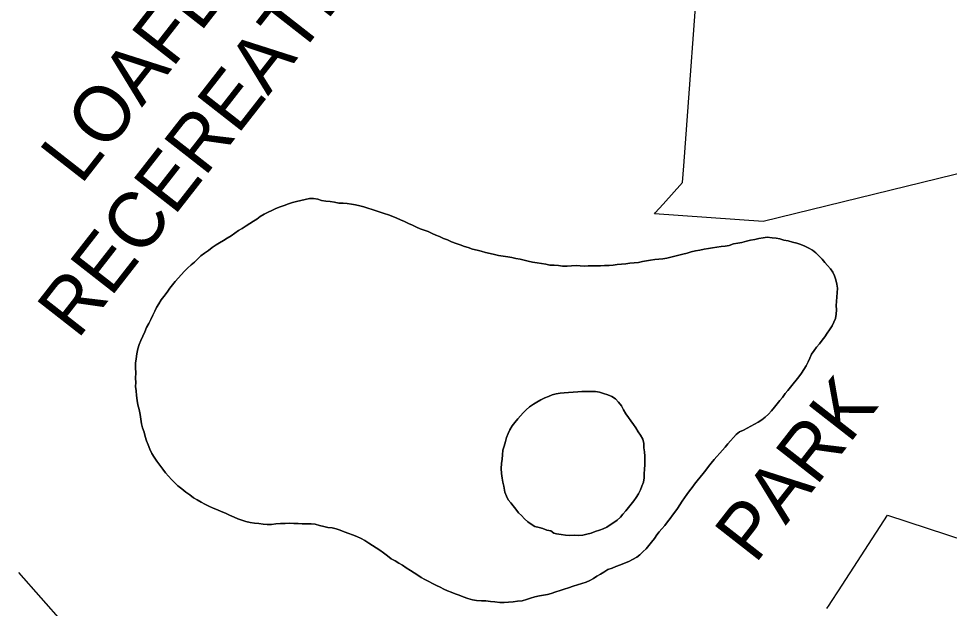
# Model space of a CAD drawing. Extents: x 586326 to 623965, y 4819854 to 4857850.
# Drawn here: x 596412.8 to 596748.3, y 4841778.5 to 4841991 of the extents above; entities that cross this region are included whole.
import ezdxf

# ---------------------------------------------------------------- set-up
doc = ezdxf.new("R2010")
doc.units = 0
for name, color, linetype in [('Park Lbls', 7, 'Continuous'), ('Park Outlines', 7, 'Continuous'), ('Rec Lbls', 7, 'Continuous')]:
    doc.layers.add(name, color=color, linetype=linetype)

msp = doc.modelspace()

# ---------------------------------------------------------------- linework, layer by layer
at = {"layer": 'Park Outlines'}
for points in [[(596784.29, 4841943.2), (596681.13, 4841917.86), (596641.99, 4841920.73), (596642.25, 4841921.02), (596645.09, 4841924.15), (596652.13, 4841931.92), (596652.57, 4841937.95), (596658.49, 4842018.07)], [(596704.13, 4841778.41), (596704.96, 4841779.69), (596705.79, 4841780.97), (596708.31, 4841784.85), (596725.99, 4841812.09), (596804.1, 4841786.56)], [(596412.71, 4841791.49), (596420.8, 4841782.34), (596428.89, 4841773.19)]]:
    msp.add_lwpolyline(points, dxfattribs=at)
for points in [[(596587.75, 4841780.62), (596586.22, 4841780.67), (596584.48, 4841780.85), (596582.85, 4841781.01), (596581.19, 4841781.17), (596579.62, 4841781.17), (596577.82, 4841781.29), (596576.41, 4841781.54), (596574.68, 4841782.11), (596573.01, 4841782.71), (596571.63, 4841783.23), (596570.12, 4841783.8), (596568.71, 4841784.38), (596567.37, 4841784.89), (596566.03, 4841785.45), (596564.69, 4841786.11), (596563.36, 4841786.77), (596562.02, 4841787.43), (596560.62, 4841788.19), (596559.23, 4841788.96), (596557.91, 4841789.68), (596556.66, 4841790.46), (596555.3, 4841791.32), (596554.03, 4841792.11), (596552.5, 4841793.11), (596551.15, 4841794.03), (596549.88, 4841794.82), (596548.53, 4841795.6), (596547.12, 4841796.4), (596545.73, 4841797.4), (596544.3, 4841798.53), (596542.97, 4841799.48), (596541.66, 4841800.3), (596540.34, 4841801.21), (596539.04, 4841802.06), (596537.53, 4841802.96), (596536.22, 4841803.65), (596534.71, 4841804.41), (596533.18, 4841804.97), (596531.8, 4841805.52), (596530.1, 4841806.14), (596528.63, 4841806.72), (596527.2, 4841807.21), (596525.76, 4841807.51), (596524.22, 4841807.64), (596522.77, 4841808.02), (596521.25, 4841808.4), (596519.72, 4841808.81), (596518.2, 4841808.96), (596516.61, 4841808.95), (596515.04, 4841809.03), (596513.51, 4841809.08), (596512, 4841809.11), (596510.47, 4841809.16), (596508.83, 4841809.15), (596507.13, 4841809.12), (596505.5, 4841808.92), (596503.89, 4841808.77), (596502.34, 4841808.7), (596500.88, 4841808.8), (596499.33, 4841809.09), (596497.76, 4841809.27), (596496.3, 4841809.45), (596494.63, 4841809.83), (596493.22, 4841810.26), (596491.82, 4841810.79), (596490.45, 4841811.36), (596488.82, 4841812.11), (596487.34, 4841812.78), (596485.83, 4841813.4), (596484.43, 4841813.97), (596482.88, 4841814.64), (596481.3, 4841815.4), (596479.92, 4841816.09), (596478.54, 4841816.79), (596477.08, 4841817.62), (596475.87, 4841818.4), (596474.44, 4841819.39), (596473.06, 4841820.41), (596471.59, 4841821.58), (596470.16, 4841822.72), (596468.95, 4841823.82), (596467.92, 4841824.9), (596466.8, 4841826.16), (596465.68, 4841827.37), (596464.73, 4841828.64), (596463.69, 4841830.09), (596462.55, 4841831.54), (596461.66, 4841832.95), (596460.84, 4841834.36), (596460.12, 4841835.92), (596459.49, 4841837.47), (596458.92, 4841838.91), (596458.44, 4841840.42), (596457.99, 4841842.06), (596457.47, 4841843.6), (596457.07, 4841845.02), (596456.82, 4841846.64), (596456.56, 4841848.38), (596456.24, 4841850.13), (596455.8, 4841851.82), (596455.48, 4841853.39), (596455.28, 4841855.16), (596455.1, 4841856.86), (596454.95, 4841858.41), (596454.98, 4841859.88), (596454.96, 4841861.5), (596455.01, 4841863.36), (596454.93, 4841865.18), (596454.94, 4841866.84), (596455.12, 4841868.45), (596455.44, 4841870.27), (596455.75, 4841872), (596456.24, 4841873.57), (596456.85, 4841875.03), (596457.6, 4841876.62), (596458.28, 4841878.2), (596458.92, 4841879.69), (596459.72, 4841881.21), (596460.42, 4841882.55), (596461.2, 4841884.12), (596461.9, 4841885.64), (596462.54, 4841886.91), (596463.27, 4841888.19), (596464.2, 4841889.64), (596465.13, 4841890.95), (596466.3, 4841892.46), (596467.34, 4841893.86), (596468.3, 4841895.07), (596469.24, 4841896.25), (596470.37, 4841897.58), (596471.39, 4841898.73), (596472.55, 4841900), (596473.7, 4841901.13), (596474.99, 4841902.33), (596476.16, 4841903.3), (596477.23, 4841904.38), (596478.5, 4841905.52), (596479.82, 4841906.48), (596481.23, 4841907.47), (596482.59, 4841908.54), (596483.96, 4841909.53), (596485.22, 4841910.25), (596486.69, 4841911.08), (596487.96, 4841911.86), (596489.36, 4841912.79), (596490.67, 4841913.75), (596491.99, 4841914.64), (596493.32, 4841915.44), (596494.78, 4841916.4), (596496.15, 4841917.16), (596497.42, 4841917.98), (596498.63, 4841918.81), (596499.88, 4841919.74), (596501.27, 4841920.57), (596502.69, 4841921.3), (596504.02, 4841921.92), (596505.51, 4841922.6), (596507.1, 4841923.23), (596508.49, 4841923.73), (596510.11, 4841924.26), (596511.53, 4841924.81), (596512.91, 4841925.17), (596514.52, 4841925.54), (596516.07, 4841925.84), (596517.63, 4841926.2), (596519.11, 4841926.23), (596520.61, 4841925.91), (596521.98, 4841925.48), (596523.54, 4841925.19), (596525.1, 4841925.08), (596526.7, 4841924.9), (596528.16, 4841924.54), (596529.75, 4841924.51), (596531.21, 4841924.38), (596532.76, 4841924.13), (596534.17, 4841923.88), (596535.78, 4841923.52), (596537.18, 4841923.17), (596538.65, 4841922.73), (596540.21, 4841922.25), (596541.67, 4841921.79), (596543.13, 4841921.25), (596544.56, 4841920.8), (596546.14, 4841920.31), (596547.69, 4841919.74), (596549.1, 4841919.12), (596550.41, 4841918.52), (596551.87, 4841917.88), (596553.3, 4841917.25), (596554.76, 4841916.56), (596556.14, 4841915.86), (596557.53, 4841915.27), (596559.01, 4841914.75), (596560.42, 4841914.28), (596561.86, 4841913.65), (596563.15, 4841913.03), (596564.53, 4841912.47), (596565.96, 4841911.85), (596567.37, 4841911.27), (596568.83, 4841910.63), (596570.44, 4841910.04), (596571.94, 4841909.5), (596573.45, 4841908.96), (596574.84, 4841908.51), (596576.4, 4841908), (596578.05, 4841907.6), (596579.51, 4841907.24), (596581.05, 4841906.74), (596582.71, 4841906.44), (596584.35, 4841905.98), (596585.81, 4841905.66), (596587.4, 4841905.45), (596589.1, 4841905.16), (596590.57, 4841904.9), (596591.98, 4841904.62), (596593.55, 4841904.29), (596594.98, 4841903.98), (596596.41, 4841903.62), (596597.97, 4841903.25), (596599.67, 4841902.99), (596601.24, 4841902.77), (596602.81, 4841902.54), (596604.2, 4841902.23), (596605.84, 4841902.14), (596607.38, 4841902.01), (596608.8, 4841901.82), (596610.45, 4841901.83), (596612.04, 4841901.91), (596613.7, 4841902.02), (596615.19, 4841901.96), (596616.68, 4841901.87), (596618.12, 4841901.89), (596619.55, 4841901.99), (596621.04, 4841901.98), (596622.56, 4841901.97), (596624.02, 4841902.02), (596625.6, 4841902.07), (596627.09, 4841902.2), (596628.56, 4841902.45), (596630.12, 4841902.53), (596631.62, 4841902.68), (596633.1, 4841902.89), (596634.66, 4841902.97), (596636.18, 4841903.14), (596637.6, 4841903.51), (596639.06, 4841903.77), (596640.51, 4841904), (596642.06, 4841904.2), (596643.59, 4841904.29), (596645.03, 4841904.46), (596646.49, 4841904.72), (596647.92, 4841905.01), (596649.36, 4841905.4), (596650.77, 4841905.84), (596652.19, 4841906.17), (596653.72, 4841906.52), (596655.18, 4841907.04), (596656.77, 4841907.38), (596658.37, 4841907.64), (596659.88, 4841907.9), (596661.48, 4841908.16), (596662.92, 4841908.47), (596664.48, 4841908.69), (596666.04, 4841908.95), (596667.47, 4841909.05), (596668.91, 4841909.29), (596670.41, 4841909.81), (596672, 4841910.16), (596673.51, 4841910.41), (596675.12, 4841910.78), (596676.54, 4841911.14), (596678.17, 4841911.45), (596679.59, 4841911.78), (596681.17, 4841912.06), (596682.59, 4841912.24), (596684.34, 4841912.05), (596685.8, 4841911.87), (596687.21, 4841911.63), (596688.6, 4841911.22), (596690.18, 4841910.91), (596691.77, 4841910.52), (596693.34, 4841910.11), (596694.73, 4841909.66), (596696.18, 4841909.06), (596697.59, 4841908.3), (596698.98, 4841907.53), (596700.16, 4841906.63), (596701.32, 4841905.48), (596702.4, 4841904.36), (596703.4, 4841903.13), (596704.36, 4841902.05), (596705.44, 4841900.89), (596706.23, 4841899.68), (596706.81, 4841898.34), (596707.32, 4841896.88), (596707.72, 4841895.32), (596707.99, 4841893.91), (596707.81, 4841892.22), (596707.66, 4841890.74), (596707.54, 4841889.12), (596707.51, 4841887.61), (596707.6, 4841886.12), (596707.44, 4841884.5), (596707.22, 4841882.99), (596706.65, 4841881.62), (596705.99, 4841880.29), (596705.11, 4841878.87), (596704.24, 4841877.63), (596703.35, 4841876.37), (596702.39, 4841875.16), (596701.4, 4841873.87), (596700.4, 4841872.62), (596699.48, 4841871.46), (596698.6, 4841870.08), (596697.96, 4841868.68), (596697.39, 4841867.32), (596696.66, 4841865.89), (596695.8, 4841864.54), (596694.92, 4841863.3), (596693.98, 4841861.97), (596693.04, 4841860.79), (596691.97, 4841859.45), (596691.05, 4841858.28), (596690.07, 4841857.05), (596689.14, 4841855.89), (596688.08, 4841854.55), (596687.19, 4841853.43), (596686.17, 4841852.2), (596685.2, 4841850.97), (596684.16, 4841849.71), (596683.06, 4841848.51), (596681.9, 4841847.47), (596680.65, 4841846.45), (596679.35, 4841845.55), (596678.03, 4841844.85), (596676.69, 4841844.17), (596675.39, 4841843.45), (596674.12, 4841842.78), (596672.65, 4841842.12), (596671.42, 4841841.17), (596670.45, 4841840.08), (596669.4, 4841838.91), (596668.43, 4841837.82), (596667.45, 4841836.59), (596666.5, 4841835.53), (596665.56, 4841834.45), (596664.46, 4841833.24), (596663.49, 4841832.12), (596662.45, 4841830.8), (596661.49, 4841829.59), (596660.47, 4841828.32), (596659.5, 4841827.09), (596658.43, 4841825.75), (596657.38, 4841824.43), (596656.46, 4841823.27), (596655.52, 4841822.08), (596654.57, 4841820.9), (596653.59, 4841819.57), (596652.78, 4841818.32), (596651.98, 4841817.09), (596651.15, 4841815.81), (596650.26, 4841814.51), (596649.3, 4841813.2), (596648.45, 4841812.05), (596647.59, 4841810.88), (596646.69, 4841809.7), (596645.68, 4841808.42), (596644.66, 4841807.15), (596643.71, 4841806.04), (596642.78, 4841804.96), (596641.93, 4841803.67), (596640.92, 4841802.35), (596640, 4841801.19), (596638.98, 4841799.96), (596637.94, 4841798.96), (596636.69, 4841797.81), (596635.57, 4841796.91), (596634.1, 4841796.07), (596632.71, 4841795.46), (596631.2, 4841794.8), (596629.67, 4841794.16), (596628.09, 4841793.55), (596626.67, 4841793), (596625.15, 4841792.46), (596623.74, 4841791.61), (596622.5, 4841790.78), (596621.21, 4841790.09), (596619.97, 4841789.25), (596618.73, 4841788.52), (596617.3, 4841787.91), (596615.78, 4841787.51), (596614.25, 4841787.05), (596612.66, 4841786.53), (596611.02, 4841785.97), (596609.48, 4841785.41), (596608.01, 4841784.94), (596606.43, 4841784.48), (596604.79, 4841783.92), (596603.39, 4841783.54), (596601.96, 4841783.25), (596600.54, 4841783.03), (596598.84, 4841782.67), (596597.28, 4841782.23), (596595.84, 4841781.7), (596594.33, 4841781.23), (596592.56, 4841781.06), (596591.09, 4841780.92), (596589.36, 4841780.76)], [(596488.82, 4841812.11), (596490.45, 4841811.36), (596491.82, 4841810.79), (596493.22, 4841810.26), (596494.63, 4841809.83), (596496.3, 4841809.45), (596497.76, 4841809.27), (596499.33, 4841809.09), (596500.88, 4841808.8), (596502.34, 4841808.7), (596503.89, 4841808.77), (596505.5, 4841808.92), (596507.13, 4841809.12), (596508.83, 4841809.15), (596510.47, 4841809.16), (596512, 4841809.11), (596513.51, 4841809.08), (596515.04, 4841809.03), (596516.61, 4841808.95), (596518.2, 4841808.96), (596519.72, 4841808.81), (596521.25, 4841808.4), (596522.77, 4841808.02), (596524.22, 4841807.64), (596525.76, 4841807.51), (596527.2, 4841807.21), (596528.63, 4841806.72), (596530.1, 4841806.14), (596531.8, 4841805.52), (596533.18, 4841804.97), (596534.71, 4841804.41), (596536.22, 4841803.65), (596537.53, 4841802.96), (596539.04, 4841802.06), (596540.34, 4841801.21), (596541.66, 4841800.3), (596542.97, 4841799.48), (596544.3, 4841798.53), (596545.73, 4841797.4), (596547.12, 4841796.4), (596548.53, 4841795.6), (596549.88, 4841794.82), (596551.15, 4841794.03), (596552.5, 4841793.11), (596554.03, 4841792.11), (596555.3, 4841791.32), (596556.66, 4841790.46), (596557.91, 4841789.68), (596559.23, 4841788.96), (596560.62, 4841788.19), (596562.02, 4841787.43), (596563.36, 4841786.77), (596564.69, 4841786.11), (596566.03, 4841785.45), (596567.37, 4841784.89), (596568.71, 4841784.38), (596570.12, 4841783.8), (596571.63, 4841783.23), (596573.01, 4841782.71), (596574.68, 4841782.11), (596576.41, 4841781.54), (596577.82, 4841781.29), (596579.62, 4841781.17), (596581.19, 4841781.17), (596582.85, 4841781.01), (596584.48, 4841780.85), (596586.22, 4841780.67), (596587.75, 4841780.62), (596589.36, 4841780.76), (596591.09, 4841780.92), (596592.56, 4841781.06), (596594.33, 4841781.23), (596595.84, 4841781.7), (596597.28, 4841782.23), (596598.84, 4841782.67), (596600.54, 4841783.03), (596601.96, 4841783.25), (596603.39, 4841783.54), (596604.79, 4841783.92), (596606.43, 4841784.48), (596608.01, 4841784.94), (596609.48, 4841785.41), (596611.02, 4841785.97), (596612.66, 4841786.53), (596614.25, 4841787.05), (596615.78, 4841787.51), (596617.3, 4841787.91), (596618.73, 4841788.52), (596619.97, 4841789.25), (596621.21, 4841790.09), (596622.5, 4841790.78), (596623.74, 4841791.61), (596625.15, 4841792.46), (596626.67, 4841793), (596628.09, 4841793.55), (596629.67, 4841794.16), (596631.2, 4841794.8), (596632.71, 4841795.46), (596634.1, 4841796.07), (596635.57, 4841796.91), (596636.69, 4841797.81), (596637.94, 4841798.96), (596638.98, 4841799.96), (596640, 4841801.19), (596640.92, 4841802.35), (596641.93, 4841803.67), (596642.78, 4841804.96), (596643.71, 4841806.04), (596644.66, 4841807.15), (596645.68, 4841808.42), (596646.69, 4841809.7), (596647.59, 4841810.88), (596648.45, 4841812.05), (596649.3, 4841813.2), (596650.26, 4841814.51), (596651.15, 4841815.81), (596651.98, 4841817.09), (596652.78, 4841818.32), (596653.59, 4841819.57), (596654.57, 4841820.9), (596655.52, 4841822.08), (596656.46, 4841823.27), (596657.38, 4841824.43), (596658.43, 4841825.75), (596659.5, 4841827.09), (596660.47, 4841828.32), (596661.49, 4841829.59), (596662.45, 4841830.8), (596663.49, 4841832.12), (596664.46, 4841833.24), (596665.56, 4841834.45), (596666.5, 4841835.53), (596667.45, 4841836.59), (596668.43, 4841837.82), (596669.4, 4841838.91), (596670.45, 4841840.08), (596671.42, 4841841.17), (596672.65, 4841842.12), (596674.12, 4841842.78), (596675.39, 4841843.45), (596676.69, 4841844.17), (596678.03, 4841844.85), (596679.35, 4841845.55), (596680.65, 4841846.45), (596681.9, 4841847.47), (596683.06, 4841848.51), (596684.16, 4841849.71), (596685.2, 4841850.97), (596686.17, 4841852.2), (596687.19, 4841853.43), (596688.08, 4841854.55), (596689.14, 4841855.89), (596690.07, 4841857.05), (596691.05, 4841858.28), (596691.97, 4841859.45), (596693.04, 4841860.79), (596693.98, 4841861.97), (596694.92, 4841863.3), (596695.8, 4841864.54), (596696.66, 4841865.89), (596697.39, 4841867.32), (596697.96, 4841868.68), (596698.6, 4841870.08), (596699.48, 4841871.46), (596700.4, 4841872.62), (596701.4, 4841873.87), (596702.39, 4841875.16), (596703.35, 4841876.37), (596704.24, 4841877.63), (596705.11, 4841878.87), (596705.99, 4841880.29), (596706.65, 4841881.62), (596707.22, 4841882.99), (596707.44, 4841884.5), (596707.6, 4841886.12), (596707.51, 4841887.61), (596707.54, 4841889.12), (596707.66, 4841890.74), (596707.81, 4841892.22), (596707.99, 4841893.91), (596707.72, 4841895.32), (596707.32, 4841896.88), (596706.81, 4841898.34), (596706.23, 4841899.68), (596705.44, 4841900.89), (596704.36, 4841902.05), (596703.4, 4841903.13), (596702.4, 4841904.36), (596701.32, 4841905.48), (596700.16, 4841906.63), (596698.98, 4841907.53), (596697.59, 4841908.3), (596696.18, 4841909.06), (596694.73, 4841909.66), (596693.34, 4841910.11), (596691.77, 4841910.52), (596690.18, 4841910.91), (596688.6, 4841911.22), (596687.21, 4841911.63), (596685.8, 4841911.87), (596684.34, 4841912.05), (596682.59, 4841912.24), (596681.17, 4841912.06), (596679.59, 4841911.78), (596678.17, 4841911.45), (596676.54, 4841911.14), (596675.12, 4841910.78), (596673.51, 4841910.41), (596672, 4841910.16), (596670.41, 4841909.81), (596668.91, 4841909.29), (596667.47, 4841909.05), (596666.04, 4841908.95), (596664.48, 4841908.69), (596662.92, 4841908.47), (596661.48, 4841908.16), (596659.88, 4841907.9), (596658.37, 4841907.64), (596656.77, 4841907.38), (596655.18, 4841907.04), (596653.72, 4841906.52), (596652.19, 4841906.17), (596650.77, 4841905.84), (596649.36, 4841905.4), (596647.92, 4841905.01), (596646.49, 4841904.72), (596645.03, 4841904.46), (596643.59, 4841904.29), (596642.06, 4841904.2), (596640.51, 4841904), (596639.06, 4841903.77), (596637.6, 4841903.51), (596636.18, 4841903.14), (596634.66, 4841902.97), (596633.1, 4841902.89), (596631.62, 4841902.68), (596630.12, 4841902.53), (596628.56, 4841902.45), (596627.09, 4841902.2), (596625.6, 4841902.07), (596624.02, 4841902.02), (596622.56, 4841901.97), (596621.04, 4841901.98), (596619.55, 4841901.99), (596618.12, 4841901.89), (596616.68, 4841901.87), (596615.19, 4841901.96), (596613.7, 4841902.02), (596612.04, 4841901.91), (596610.45, 4841901.83), (596608.8, 4841901.82), (596607.38, 4841902.01), (596605.84, 4841902.14), (596604.2, 4841902.23), (596602.81, 4841902.54), (596601.24, 4841902.77), (596599.67, 4841902.99), (596597.97, 4841903.25), (596596.41, 4841903.62), (596594.98, 4841903.98), (596593.55, 4841904.29), (596591.98, 4841904.62), (596590.57, 4841904.9), (596589.1, 4841905.16), (596587.4, 4841905.45), (596585.81, 4841905.66), (596584.35, 4841905.98), (596582.71, 4841906.44), (596581.05, 4841906.74), (596579.51, 4841907.24), (596578.05, 4841907.6), (596576.4, 4841908), (596574.84, 4841908.51), (596573.45, 4841908.96), (596571.94, 4841909.5), (596570.44, 4841910.04), (596568.83, 4841910.63), (596567.37, 4841911.27), (596565.96, 4841911.85), (596564.53, 4841912.47), (596563.15, 4841913.03), (596561.86, 4841913.65), (596560.42, 4841914.28), (596559.01, 4841914.75), (596557.53, 4841915.27), (596556.14, 4841915.86), (596554.76, 4841916.56), (596553.3, 4841917.25), (596551.87, 4841917.88), (596550.41, 4841918.52), (596549.1, 4841919.12), (596547.69, 4841919.74), (596546.14, 4841920.31), (596544.56, 4841920.8), (596543.13, 4841921.25), (596541.67, 4841921.79), (596540.21, 4841922.25), (596538.65, 4841922.73), (596537.18, 4841923.17), (596535.78, 4841923.52), (596534.17, 4841923.88), (596532.76, 4841924.13), (596531.21, 4841924.38), (596529.75, 4841924.51), (596528.16, 4841924.54), (596526.7, 4841924.9), (596525.1, 4841925.08), (596523.54, 4841925.19), (596521.98, 4841925.48), (596520.61, 4841925.91), (596519.11, 4841926.23), (596517.63, 4841926.2), (596516.07, 4841925.84), (596514.52, 4841925.54), (596512.91, 4841925.17), (596511.53, 4841924.81), (596510.11, 4841924.26), (596508.49, 4841923.73), (596507.1, 4841923.23), (596505.51, 4841922.6), (596504.02, 4841921.92), (596502.69, 4841921.3), (596501.27, 4841920.57), (596499.88, 4841919.74), (596498.63, 4841918.81), (596497.42, 4841917.98), (596496.15, 4841917.16), (596494.78, 4841916.4), (596493.32, 4841915.44), (596491.99, 4841914.64), (596490.67, 4841913.75), (596489.36, 4841912.79), (596487.96, 4841911.86), (596486.69, 4841911.08), (596485.22, 4841910.25), (596483.96, 4841909.53), (596482.59, 4841908.54), (596481.23, 4841907.47), (596479.82, 4841906.48), (596478.5, 4841905.52), (596477.23, 4841904.38), (596476.16, 4841903.3), (596474.99, 4841902.33), (596473.7, 4841901.13), (596472.55, 4841900), (596471.39, 4841898.73), (596470.37, 4841897.58), (596469.24, 4841896.25), (596468.3, 4841895.07), (596467.34, 4841893.86), (596466.3, 4841892.46), (596465.13, 4841890.95), (596464.2, 4841889.64), (596463.27, 4841888.19), (596462.54, 4841886.91), (596461.9, 4841885.64), (596461.2, 4841884.12), (596460.42, 4841882.55), (596459.72, 4841881.21), (596458.92, 4841879.69), (596458.28, 4841878.2), (596457.6, 4841876.62), (596456.85, 4841875.03), (596456.24, 4841873.57), (596455.75, 4841872), (596455.44, 4841870.27), (596455.12, 4841868.45), (596454.94, 4841866.84), (596454.93, 4841865.18), (596455.01, 4841863.36), (596454.96, 4841861.5), (596454.98, 4841859.88), (596454.95, 4841858.41), (596455.1, 4841856.86), (596455.28, 4841855.16), (596455.48, 4841853.39), (596455.8, 4841851.82), (596456.24, 4841850.13), (596456.56, 4841848.38), (596456.82, 4841846.64), (596457.07, 4841845.02), (596457.47, 4841843.6), (596457.99, 4841842.06), (596458.44, 4841840.42), (596458.92, 4841838.91), (596459.49, 4841837.47), (596460.12, 4841835.92), (596460.84, 4841834.36), (596461.66, 4841832.95), (596462.55, 4841831.54), (596463.69, 4841830.09), (596464.73, 4841828.64), (596465.68, 4841827.37), (596466.8, 4841826.16), (596467.92, 4841824.9), (596468.95, 4841823.82), (596470.16, 4841822.72), (596471.59, 4841821.58), (596473.06, 4841820.41), (596474.44, 4841819.39), (596475.87, 4841818.4), (596477.08, 4841817.62), (596478.54, 4841816.79), (596479.92, 4841816.09), (596481.3, 4841815.4), (596482.88, 4841814.64), (596484.43, 4841813.97), (596485.83, 4841813.4), (596487.34, 4841812.78)], [(596611.5, 4841804.76), (596612.99, 4841804.85), (596614.54, 4841804.82), (596616.13, 4841804.94), (596617.58, 4841805.21), (596619.11, 4841805.67), (596620.62, 4841806.19), (596622.12, 4841806.7), (596623.51, 4841807.21), (596624.82, 4841807.8), (596626.03, 4841808.59), (596627.3, 4841809.45), (596628.49, 4841810.25), (596629.68, 4841811.39), (596630.63, 4841812.45), (596631.68, 4841813.63), (596632.61, 4841814.85), (596633.52, 4841816.03), (596634.49, 4841817.3), (596635.33, 4841818.49), (596636.17, 4841819.79), (596636.91, 4841821.17), (596637.45, 4841822.49), (596637.98, 4841823.94), (596638.2, 4841825.55), (596638.27, 4841827.02), (596638.37, 4841828.65), (596638.45, 4841830.27), (596638.47, 4841831.75), (596638.45, 4841833.34), (596638.39, 4841834.87), (596638.19, 4841836.31), (596638.11, 4841837.87), (596637.73, 4841839.45), (596636.9, 4841840.88), (596636.04, 4841842.14), (596635.21, 4841843.53), (596634.4, 4841844.72), (596633.48, 4841846.08), (596632.56, 4841847.31), (596631.7, 4841848.66), (596630.84, 4841850.1), (596630.05, 4841851.54), (596629.05, 4841852.81), (596627.96, 4841854), (596626.62, 4841854.88), (596625.15, 4841855.51), (596623.65, 4841855.97), (596622.14, 4841856.4), (596620.66, 4841856.7), (596619, 4841856.68), (596617.4, 4841856.64), (596615.81, 4841856.66), (596614.3, 4841856.59), (596612.67, 4841856.42), (596611.02, 4841856.27), (596609.41, 4841856.13), (596607.93, 4841856.1), (596606.5, 4841855.82), (596605.08, 4841855.45), (596603.72, 4841854.89), (596602.4, 4841854.33), (596601, 4841853.63), (596599.57, 4841852.83), (596598.32, 4841852.04), (596596.97, 4841851.17), (596595.69, 4841850.11), (596594.65, 4841848.94), (596593.69, 4841847.87), (596592.74, 4841846.81), (596591.68, 4841845.53), (596590.69, 4841844.24), (596589.81, 4841842.86), (596589.19, 4841841.57), (596588.65, 4841840.07), (596588.29, 4841838.6), (596587.75, 4841836.95), (596587.36, 4841835.51), (596587.17, 4841833.8), (596587.06, 4841832.28), (596586.88, 4841830.68), (596586.73, 4841828.93), (596586.82, 4841827.12), (596587.02, 4841825.49), (596587.33, 4841824.01), (596587.68, 4841822.6), (596588, 4841820.34), (596588.6, 4841818.99), (596589.24, 4841817.68), (596590.15, 4841816.59), (596591.02, 4841815.42), (596591.99, 4841814.21), (596592.96, 4841812.96), (596594.01, 4841811.95), (596595.11, 4841810.75), (596596.38, 4841809.74), (596597.56, 4841808.8), (596598.89, 4841808.03), (596600.36, 4841807.63), (596601.78, 4841807.27), (596603.14, 4841806.73), (596604.59, 4841806.49), (596605.74, 4841805.59), (596606.71, 4841805.35), (596608.3, 4841805.15), (596609.92, 4841804.84)], [(596587.68, 4841822.6), (596587.33, 4841824.01), (596587.02, 4841825.49), (596586.82, 4841827.12), (596586.73, 4841828.93), (596586.88, 4841830.68), (596587.06, 4841832.28), (596587.17, 4841833.8), (596587.36, 4841835.51), (596587.75, 4841836.95), (596588.29, 4841838.6), (596588.65, 4841840.07), (596589.19, 4841841.57), (596589.81, 4841842.86), (596590.69, 4841844.24), (596591.68, 4841845.53), (596592.74, 4841846.81), (596593.69, 4841847.87), (596594.65, 4841848.94), (596595.69, 4841850.11), (596596.97, 4841851.17), (596598.32, 4841852.04), (596599.57, 4841852.83), (596601, 4841853.63), (596602.4, 4841854.33), (596603.72, 4841854.89), (596605.08, 4841855.45), (596606.5, 4841855.82), (596607.93, 4841856.1), (596609.41, 4841856.13), (596611.02, 4841856.27), (596612.67, 4841856.42), (596614.3, 4841856.59), (596615.81, 4841856.66), (596617.4, 4841856.64), (596619, 4841856.68), (596620.66, 4841856.7), (596622.14, 4841856.4), (596623.65, 4841855.97), (596625.15, 4841855.51), (596626.62, 4841854.88), (596627.96, 4841854), (596629.05, 4841852.81), (596630.05, 4841851.54), (596630.84, 4841850.1), (596631.7, 4841848.66), (596632.56, 4841847.31), (596633.48, 4841846.08), (596634.4, 4841844.72), (596635.21, 4841843.53), (596636.04, 4841842.14), (596636.9, 4841840.88), (596637.73, 4841839.45), (596638.11, 4841837.87), (596638.19, 4841836.31), (596638.39, 4841834.87), (596638.45, 4841833.34), (596638.47, 4841831.75), (596638.45, 4841830.27), (596638.37, 4841828.65), (596638.27, 4841827.02), (596638.2, 4841825.55), (596637.98, 4841823.94), (596637.45, 4841822.49), (596636.91, 4841821.17), (596636.17, 4841819.79), (596635.33, 4841818.49), (596634.49, 4841817.3), (596633.52, 4841816.03), (596632.61, 4841814.85), (596631.68, 4841813.63), (596630.63, 4841812.45), (596629.68, 4841811.39), (596628.49, 4841810.25), (596627.3, 4841809.45), (596626.03, 4841808.59), (596624.82, 4841807.8), (596623.51, 4841807.21), (596622.12, 4841806.7), (596620.62, 4841806.19), (596619.11, 4841805.67), (596617.58, 4841805.21), (596616.13, 4841804.94), (596614.54, 4841804.82), (596612.99, 4841804.85), (596611.5, 4841804.76), (596609.92, 4841804.84), (596608.3, 4841805.15), (596606.71, 4841805.35), (596605.74, 4841805.59), (596604.59, 4841806.49), (596603.14, 4841806.73), (596601.78, 4841807.27), (596600.36, 4841807.63), (596598.89, 4841808.03), (596597.56, 4841808.8), (596596.38, 4841809.74), (596595.11, 4841810.75), (596594.01, 4841811.95), (596592.96, 4841812.96), (596591.99, 4841814.21), (596591.02, 4841815.42), (596590.15, 4841816.59), (596589.24, 4841817.68), (596588.6, 4841818.99), (596588, 4841820.34)]]:
    msp.add_lwpolyline(points, close=True, dxfattribs=at)

# ---------------------------------------------------------------- texts
at = {"layer": 'Park Lbls'}
msp.add_text('PARK', height=19.992, rotation=52, dxfattribs=at).set_placement((596678.25, 4841794.17))
at = {"layer": 'Rec Lbls'}
for s, p in [('RECEREATION CENTRE', (596434.05, 4841875.11)), ("      LOAFER'S LAKE", (596407.78, 4841895.63))]:
    msp.add_text(s, height=20, rotation=52, dxfattribs=at).set_placement(p)

doc.saveas('drawing.dxf')
